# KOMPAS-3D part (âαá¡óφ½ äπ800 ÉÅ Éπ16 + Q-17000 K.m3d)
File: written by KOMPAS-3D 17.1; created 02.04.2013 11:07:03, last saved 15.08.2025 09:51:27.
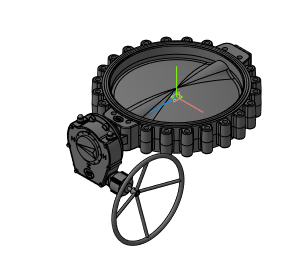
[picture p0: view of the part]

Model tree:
1. Операция без истории:5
